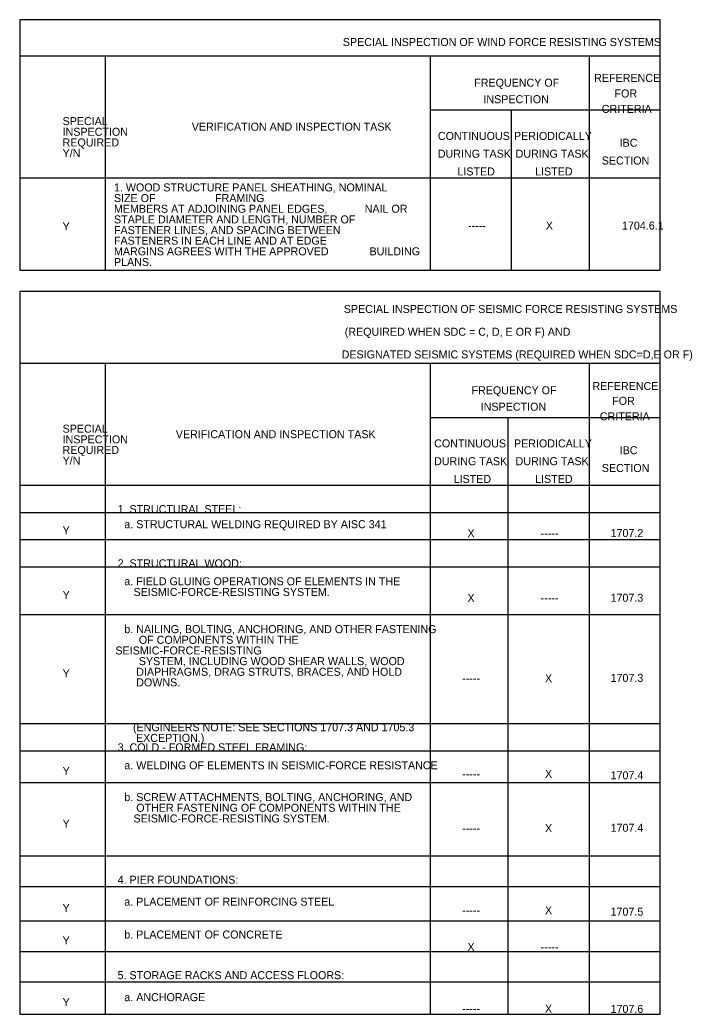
# Model space of a CAD drawing. Extents: x 2632118 to 2632142.4, y 1706724.1 to 1706788.4.
# Drawn here: x 2632135.37 to 2632142.37, y 1706778.01 to 1706788.35 of the extents above; entities that cross this region are included whole.
import ezdxf

# ---------------------------------------------------------------- set-up
doc = ezdxf.new("R2010")
doc.units = 0
doc.layers.add('Default', color=7, linetype='Continuous')

msp = doc.modelspace()

# ---------------------------------------------------------------- linework, layer by layer
at = {"layer": 'Default'}
for p, q in [((2632136.255, 1706787.976), (2632136.255, 1706785.749)), ((2632139.639, 1706787.976), (2632139.639, 1706785.749)), ((2632141.293, 1706787.976), (2632141.293, 1706785.749)), ((2632142.033, 1706787.412), (2632139.639, 1706787.412)), ((2632142.033, 1706787.412), (2632139.639, 1706787.412)), ((2632140.481, 1706787.412), (2632140.481, 1706785.749)), ((2632142.033, 1706786.706), (2632135.366, 1706786.706)), ((2632136.255, 1706784.776), (2632136.255, 1706778.006)), ((2632139.639, 1706784.776), (2632139.639, 1706778.006)), ((2632141.293, 1706784.776), (2632141.293, 1706778.006)), ((2632142.033, 1706784.211), (2632139.639, 1706784.211)), ((2632140.448, 1706784.211), (2632140.448, 1706778.006)), ((2632142.033, 1706783.506), (2632135.366, 1706783.506)), ((2632142.033, 1706783.224), (2632135.366, 1706783.224)), ((2632142.033, 1706782.941), (2632135.366, 1706782.941)), ((2632142.033, 1706782.659), (2632135.366, 1706782.659)), ((2632142.033, 1706782.161), (2632135.366, 1706782.161)), ((2632142.033, 1706781.027), (2632135.366, 1706781.027)), ((2632142.033, 1706780.744), (2632135.366, 1706780.744)), ((2632142.033, 1706780.413), (2632135.366, 1706780.413)), ((2632142.033, 1706779.649), (2632135.366, 1706779.649)), ((2632142.033, 1706779.332), (2632135.366, 1706779.332)), ((2632142.033, 1706778.973), (2632135.366, 1706778.973)), ((2632142.033, 1706778.655), (2632135.366, 1706778.655)), ((2632142.033, 1706778.338), (2632135.366, 1706778.338))]:
    msp.add_line(p, q, dxfattribs=at)
for points in [[(2632135.366, 1706785.749), (2632142.033, 1706785.749), (2632142.033, 1706788.353), (2632135.366, 1706788.353)], [(2632135.366, 1706778.006), (2632142.033, 1706778.006), (2632142.033, 1706785.527), (2632135.366, 1706785.527)]]:
    msp.add_lwpolyline(points, close=True, dxfattribs=at)
for points in [[(2632142.033, 1706787.976), (2632135.366, 1706787.976)], [(2632142.033, 1706784.776), (2632135.366, 1706784.776)]]:
    msp.add_lwpolyline(points, dxfattribs=at)

# ---------------------------------------------------------------- texts
for s, height, p in [('SPECIAL INSPECTION OF WIND FORCE RESISTING SYSTEMS', 0.08333, (2632138.729, 1706788.081)), ('REFERENCE', 0.0833, (2632141.346, 1706787.708)), ('FREQUENCY OF  ', 0.08333, (2632140.097, 1706787.658)), ('INSPECTION ', 0.08333, (2632140.193, 1706787.486)), ('FOR', 0.0833, (2632141.558, 1706787.546)), ('CRITERIA', 0.0833, (2632141.425, 1706787.385)), ('SPECIAL ', 0.0833, (2632135.811, 1706787.258)), ('VERIFICATION AND INSPECTION TASK ', 0.08333, (2632137.156, 1706787.2)), ('INSPECTION ', 0.08333, (2632135.811, 1706787.147)), ('CONTINUOUS', 0.0833, (2632139.719, 1706787.104)), ('PERIODICALLY', 0.08333, (2632140.511, 1706787.104)), ('REQUIRED', 0.0833, (2632135.811, 1706787.036)), ('IBC', 0.0833, (2632141.611, 1706787.033)), ('Y/N', 0.0833, (2632135.811, 1706786.925)), ('DURING TASK', 0.08333, (2632139.718, 1706786.919)), ('DURING TASK', 0.08333, (2632140.528, 1706786.919)), ('SECTION', 0.0833, (2632141.425, 1706786.848)), ('LISTED', 0.0833, (2632139.922, 1706786.734)), ('LISTED', 0.0833, (2632140.731, 1706786.734)), ('1. WOOD STRUCTURE PANEL SHEATHING, NOMINAL ', 0.08333, (2632136.346, 1706786.568)), ('SIZE OF                    FRAMING ', 0.08333, (2632136.346, 1706786.457)), ('MEMBERS AT ADJOINING PANEL EDGES, ', 0.08333, (2632136.346, 1706786.346)), ('NAIL OR ', 0.0833, (2632138.957, 1706786.346)), ('Y', 0.0833, (2632135.811, 1706786.162)), ('STAPLE DIAMETER AND LENGTH, NUMBER OF ', 0.08333, (2632136.346, 1706786.235)), ('X', 0.0833, (2632140.842, 1706786.171)), ('1704.6.1', 0.0833, (2632141.636, 1706786.171)), ('FASTENER LINES, AND SPACING BETWEEN ', 0.08333, (2632136.346, 1706786.124)), ('-----', 0.0833, (2632140.033, 1706786.171)), ('FASTENERS IN EACH LINE AND AT EDGE ', 0.08333, (2632136.346, 1706786.014)), ('MARGINS AGREES WITH THE APPROVED ', 0.08333, (2632136.346, 1706785.903)), ('BUILDING ', 0.0833, (2632139.007, 1706785.903)), ('PLANS.', 0.0833, (2632136.346, 1706785.792)), ('SPECIAL INSPECTION OF SEISMIC FORCE RESISTING SYSTEMS ', 0.08333, (2632138.739, 1706785.303)), ('(REQUIRED WHEN SDC = C, D, E OR F) AND', 0.08333, (2632138.749, 1706785.066)), ('DESIGNATED SEISMIC SYSTEMS (REQUIRED WHEN SDC=D,E OR F)', 0.08333, (2632138.717, 1706784.83)), ('REFERENCE', 0.0833, (2632141.328, 1706784.501)), ('FREQUENCY OF  ', 0.08333, (2632140.069, 1706784.457)), ('INSPECTION ', 0.08333, (2632140.165, 1706784.286)), ('FOR', 0.0833, (2632141.534, 1706784.347)), ('CRITERIA', 0.0833, (2632141.405, 1706784.186)), ('SPECIAL ', 0.0833, (2632135.811, 1706784.057)), ('VERIFICATION AND INSPECTION TASK ', 0.08333, (2632136.99, 1706784)), ('INSPECTION ', 0.08333, (2632135.811, 1706783.946)), ('CONTINUOUS', 0.0833, (2632139.68, 1706783.904)), ('PERIODICALLY', 0.08333, (2632140.511, 1706783.904)), ('REQUIRED', 0.0833, (2632135.811, 1706783.836)), ('IBC', 0.0833, (2632141.612, 1706783.833)), ('Y/N', 0.0833, (2632135.811, 1706783.725)), ('DURING TASK', 0.08333, (2632139.679, 1706783.719)), ('DURING TASK', 0.08333, (2632140.528, 1706783.719)), ('SECTION', 0.0833, (2632141.426, 1706783.648)), ('LISTED', 0.0833, (2632139.883, 1706783.534)), ('LISTED', 0.0833, (2632140.731, 1706783.534)), ('1. STRUCTURAL STEEL: ', 0.08333, (2632136.384, 1706783.22)), ('   a. STRUCTURAL WELDING REQUIRED BY AISC 341', 0.08333, (2632136.361, 1706783.063)), ('Y', 0.0833, (2632135.811, 1706782.999)), ('X', 0.0833, (2632140.027, 1706782.969)), ('1707.2', 0.0833, (2632141.517, 1706782.971)), ('-----', 0.0833, (2632140.789, 1706782.969)), ('2. STRUCTURAL WOOD: ', 0.08333, (2632136.384, 1706782.656)), ('   a. FIELD GLUING OPERATIONS OF ELEMENTS IN THE ', 0.08333, (2632136.361, 1706782.469)), ('Y', 0.0833, (2632135.811, 1706782.327)), ('       SEISMIC-FORCE-RESISTING SYSTEM.', 0.08333, (2632136.333, 1706782.358)), ('X', 0.0833, (2632140.027, 1706782.296)), ('-----', 0.0833, (2632140.789, 1706782.296)), ('1707.3', 0.0833, (2632141.517, 1706782.298)), ('   b. NAILING, BOLTING, ANCHORING, AND OTHER FASTENING', 0.08333, (2632136.361, 1706781.971)), ('       OF COMPONENTS WITHIN THE ', 0.08333, (2632136.388, 1706781.86)), ('SEISMIC-FORCE-RESISTING', 0.08333, (2632136.361, 1706781.749)), ('       SYSTEM, INCLUDING WOOD SHEAR WALLS, WOOD', 0.08333, (2632136.388, 1706781.638)), ('Y', 0.0833, (2632135.811, 1706781.511)), ('       DIAPHRAGMS, DRAG STRUTS, BRACES, AND HOLD ', 0.08333, (2632136.361, 1706781.527)), ('       DOWNS.', 0.08333, (2632136.361, 1706781.417)), ('-----', 0.0833, (2632139.972, 1706781.46)), ('X', 0.0833, (2632140.834, 1706781.46)), ('1707.3', 0.0833, (2632141.517, 1706781.464)), ('(ENGINEERS NOTE: SEE SECTIONS 1707.3 AND 1705.3 ', 0.08333, (2632136.544, 1706780.95)), (' EXCEPTION.)', 0.08333, (2632136.544, 1706780.839)), ('3. COLD - FORMED STEEL FRAMING: ', 0.08333, (2632136.384, 1706780.741)), ('   a. WELDING OF ELEMENTS IN SEISMIC-FORCE RESISTANCE', 0.08333, (2632136.361, 1706780.554)), ('Y', 0.0833, (2632135.811, 1706780.495)), ('X', 0.0833, (2632140.834, 1706780.465)), ('1707.4', 0.0833, (2632141.517, 1706780.45)), ('-----', 0.0833, (2632139.972, 1706780.465)), ('   b. SCREW ATTACHMENTS, BOLTING, ANCHORING, AND', 0.08333, (2632136.361, 1706780.223)), ('       OTHER FASTENING OF COMPONENTS WITHIN THE ', 0.08333, (2632136.361, 1706780.112)), ('Y', 0.0833, (2632135.811, 1706779.948)), ('Y', 0.0833, (2632135.811, 1706779.948)), ('       SEISMIC-FORCE-RESISTING SYSTEM.', 0.08333, (2632136.333, 1706780.001)), ('-----', 0.0833, (2632139.972, 1706779.9)), ('X', 0.0833, (2632140.834, 1706779.9)), ('1707.4', 0.0833, (2632141.517, 1706779.904)), ('4. PIER FOUNDATIONS: ', 0.08333, (2632136.384, 1706779.363)), ('   a. PLACEMENT OF REINFORCING STEEL', 0.08333, (2632136.361, 1706779.135)), ('Y', 0.0833, (2632135.811, 1706779.069)), ('X', 0.0833, (2632140.834, 1706779.046)), ('1707.5', 0.0833, (2632141.517, 1706779.031)), ('-----', 0.0833, (2632139.972, 1706779.046)), ('   b. PLACEMENT OF CONCRETE', 0.08333, (2632136.361, 1706778.793)), ('Y', 0.0833, (2632135.811, 1706778.731)), ('X', 0.0833, (2632140.027, 1706778.664)), ('-----', 0.0833, (2632140.789, 1706778.664)), ('5. STORAGE RACKS AND ACCESS FLOORS: ', 0.08333, (2632136.384, 1706778.37)), ('Y', 0.0833, (2632135.811, 1706778.089)), ('   a. ANCHORAGE', 0.08333, (2632136.361, 1706778.141)), ('-----', 0.0833, (2632139.972, 1706778.021)), ('X', 0.0833, (2632140.834, 1706778.021)), ('1707.6', 0.0833, (2632141.517, 1706778.019))]:
    msp.add_text(s, height=height, dxfattribs=at).set_placement(p)

doc.saveas('drawing.dxf')
